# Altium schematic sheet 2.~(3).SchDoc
size 420 x 297 mm
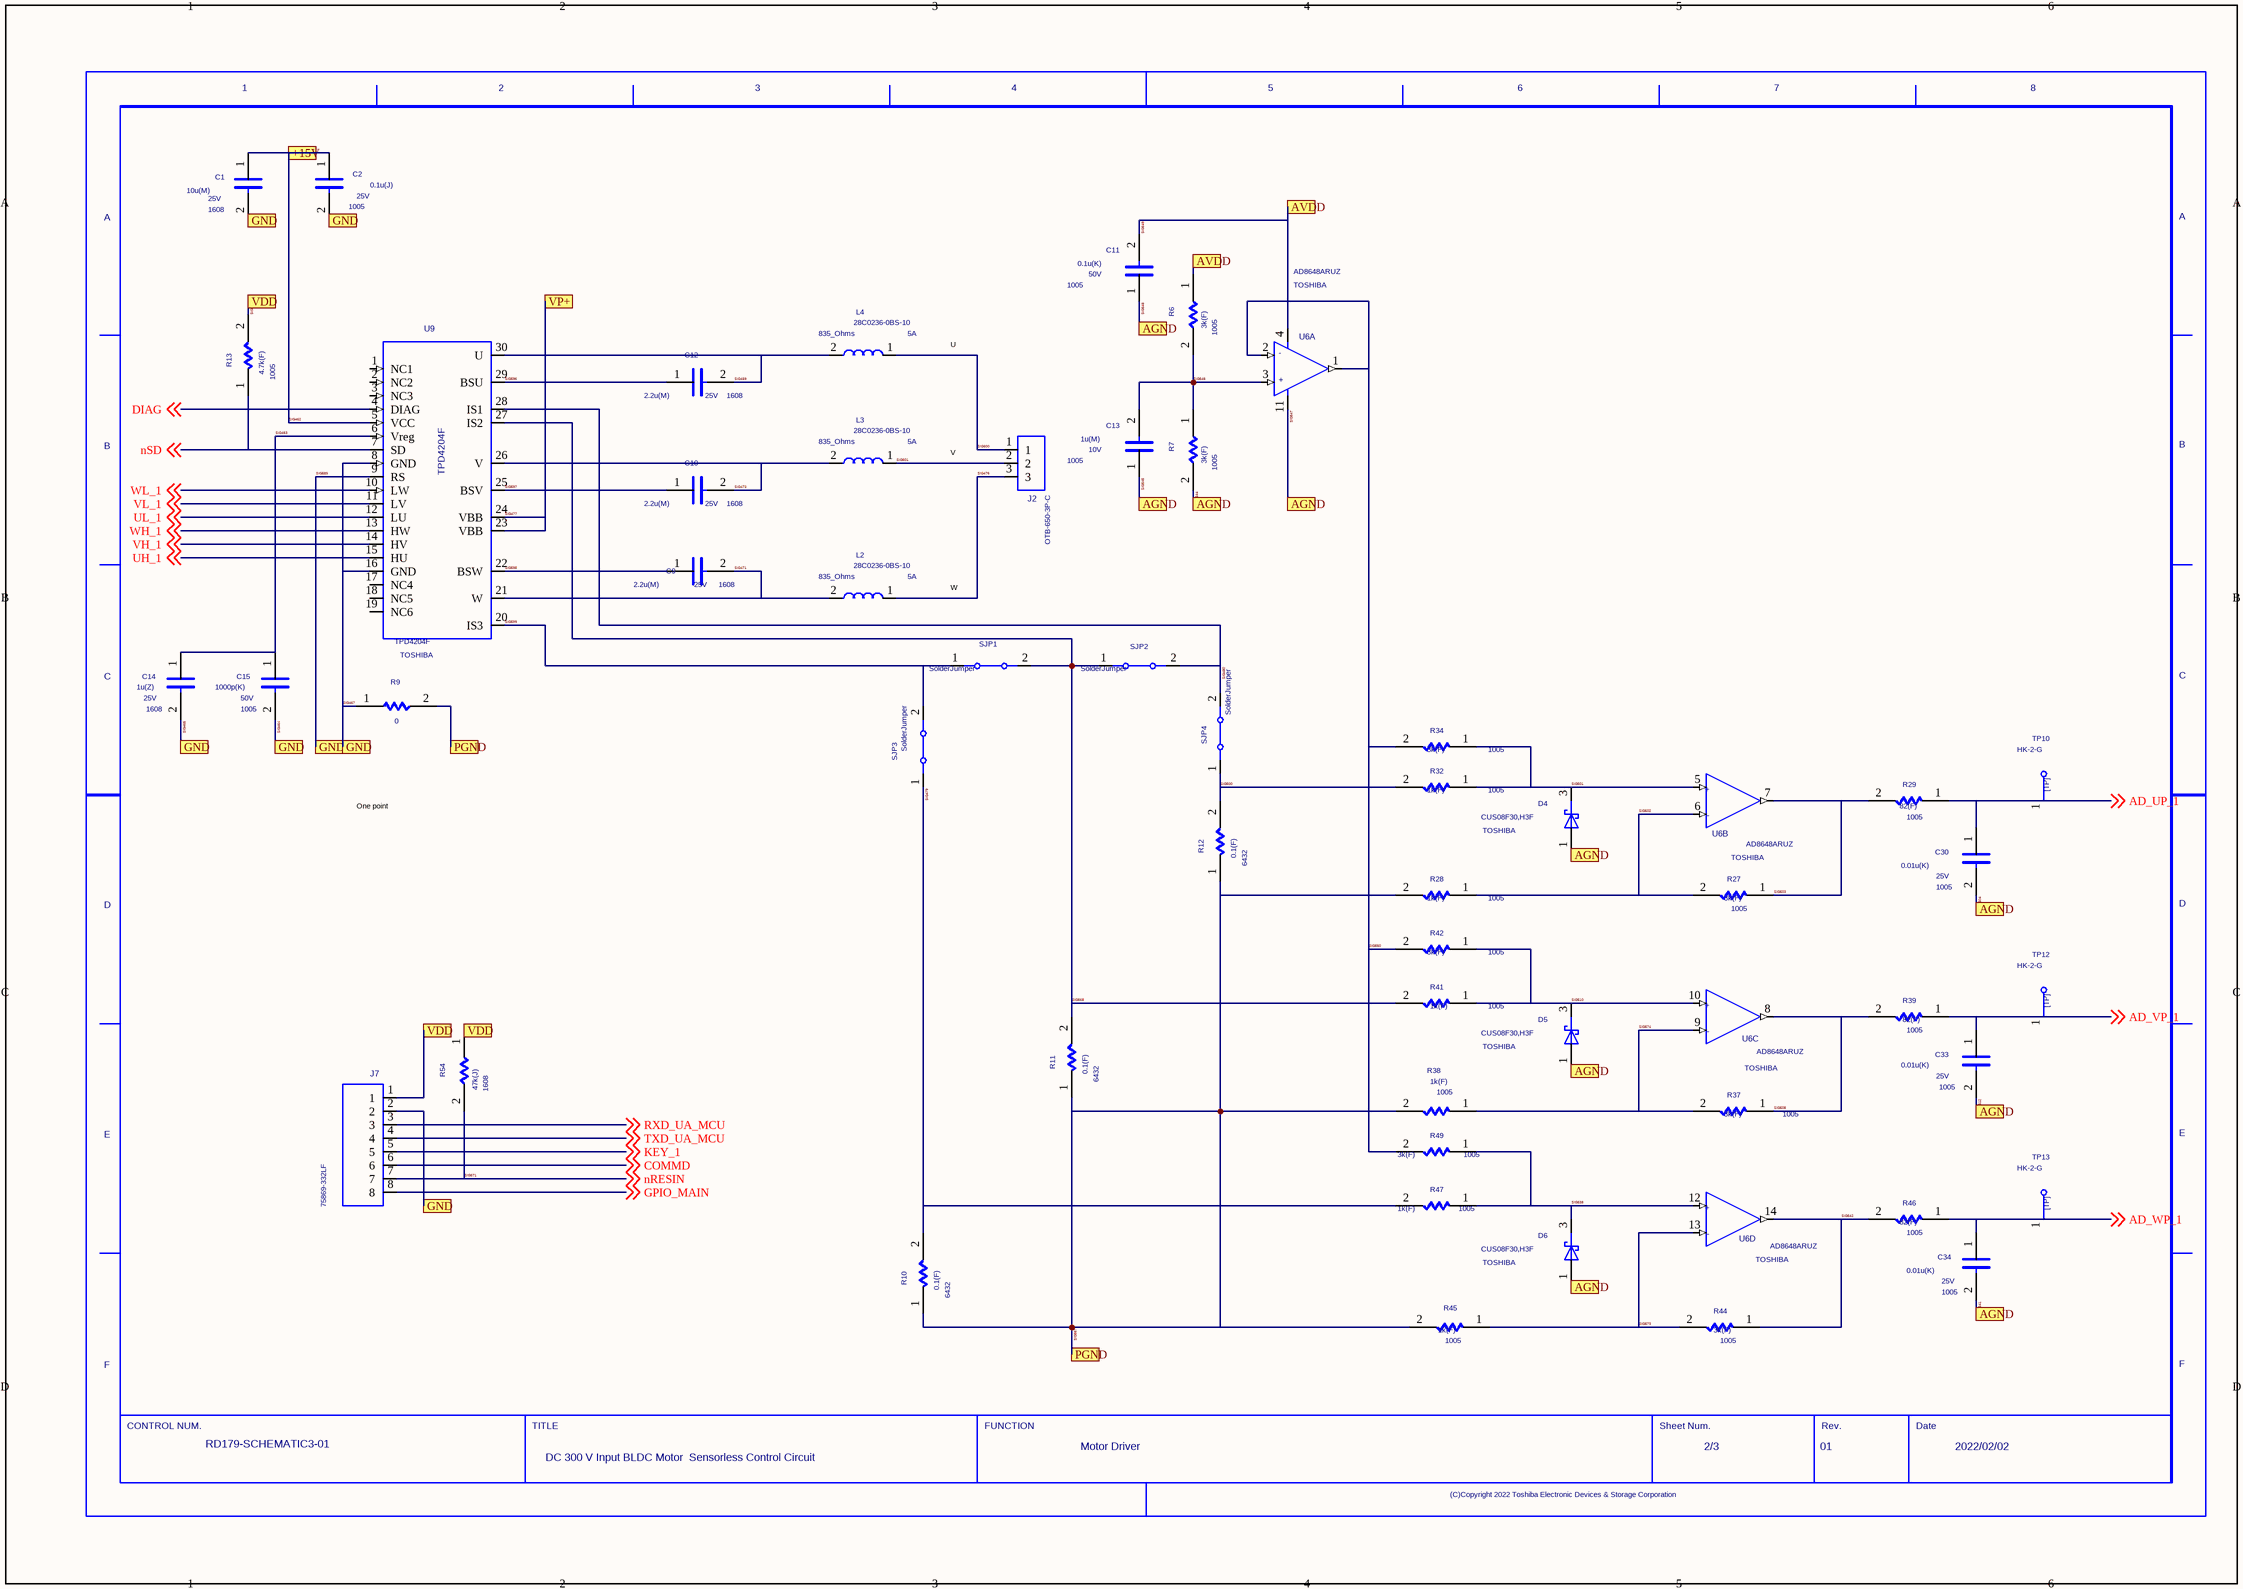
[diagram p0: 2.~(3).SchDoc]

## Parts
C1  SIZECODESMD: 1608  VAL2: 25V  VAL1: 10u(M)  (hidden comment: C)
C2  SIZECODESMD: 1005  VAL2: 25V  VAL1: 0.1u(J)  (hidden comment: C)
C9  SIZECODESMD: 1608  VAL2: 25V  VAL1: 2.2u(M)  (hidden comment: C)
C10  SIZECODESMD: 1608  VAL2: 25V  VAL1: 2.2u(M)  (hidden comment: C)
C11  SIZECODESMD: 1005  VAL2: 50V  VAL1: 0.1u(K)  (hidden comment: C)
C12  SIZECODESMD: 1608  VAL2: 25V  VAL1: 2.2u(M)  (hidden comment: C)
C13  SIZECODESMD: 1005  VAL2: 10V  VAL1: 1u(M)  (hidden comment: C)
C14  SIZECODESMD: 1608  VAL2: 25V  VAL1: 1u(Z)  (hidden comment: C)
C15  SIZECODESMD: 1005  VAL2: 50V  VAL1: 1000p(K)  (hidden comment: C)
C30  SIZECODESMD: 1005  VAL2: 25V  VAL1: 0.01u(K)  (hidden comment: C)
C33  SIZECODESMD: 1005  VAL2: 25V  VAL1: 0.01u(K)  (hidden comment: C)
C34  SIZECODESMD: 1005  VAL2: 25V  VAL1: 0.01u(K)  (hidden comment: C)
D4  USERCOMPTEXT3: TOSHIBA  VAL3: CUS08F30,H3F  (hidden comment: SBD)
D5  USERCOMPTEXT3: TOSHIBA  VAL3: CUS08F30,H3F  (hidden comment: SBD)
D6  USERCOMPTEXT3: TOSHIBA  VAL3: CUS08F30,H3F  (hidden comment: SBD)
J2  OTB-650-3P-C
J7  75869-332LF
L2  VAL3: 28C0236-0BS-10  VAL2: 5A  VAL1: 835_Ohms  (hidden comment: L)
L3  VAL3: 28C0236-0BS-10  VAL2: 5A  VAL1: 835_Ohms  (hidden comment: L)
L4  VAL3: 28C0236-0BS-10  VAL2: 5A  VAL1: 835_Ohms  (hidden comment: L)
R6  SIZECODESMD: 1005  VAL1: 3k(F)  (hidden comment: R)
R7  SIZECODESMD: 1005  VAL1: 3k(F)  (hidden comment: R)
R9  VAL1: 0  (hidden comment: R)
R10  SIZECODESMD: 6432  VAL1: 0.1(F)  (hidden comment: R)
R11  SIZECODESMD: 6432  VAL1: 0.1(F)  (hidden comment: R)
R12  SIZECODESMD: 6432  VAL1: 0.1(F)  (hidden comment: R)
R13  SIZECODESMD: 1005  VAL1: 4.7k(F)  (hidden comment: R)
R27  SIZECODESMD: 1005  VAL1: 3k(F)  (hidden comment: R)
R28  SIZECODESMD: 1005  VAL1: 1k(F)  (hidden comment: R)
R29  SIZECODESMD: 1005  VAL1: 82(F)  (hidden comment: R)
R32  SIZECODESMD: 1005  VAL1: 1k(F)  (hidden comment: R)
R34  SIZECODESMD: 1005  VAL1: 3k(F)  (hidden comment: R)
R37  SIZECODESMD: 1005  VAL1: 3k(F)  (hidden comment: R)
R38  SIZECODESMD: 1005  VAL1: 1k(F)  (hidden comment: R)
R39  SIZECODESMD: 1005  VAL1: 82(F)  (hidden comment: R)
R41  SIZECODESMD: 1005  VAL1: 1k(F)  (hidden comment: R)
R42  SIZECODESMD: 1005  VAL1: 3k(F)  (hidden comment: R)
R44  SIZECODESMD: 1005  VAL1: 3k(F)  (hidden comment: R)
R45  SIZECODESMD: 1005  VAL1: 1k(F)  (hidden comment: R)
R46  SIZECODESMD: 1005  VAL1: 82(F)  (hidden comment: R)
R47  SIZECODESMD: 1005  VAL1: 1k(F)  (hidden comment: R)
R49  SIZECODESMD: 1005  VAL1: 3k(F)  (hidden comment: R)
R54  SIZECODESMD: 1608  VAL1: 47k(J)  (hidden comment: R)
SJP1  VAL3: SolderJumper  (hidden comment: JP)
SJP2  VAL3: SolderJumper  (hidden comment: JP)
SJP3  VAL3: SolderJumper  (hidden comment: JP)
SJP4  VAL3: SolderJumper  (hidden comment: JP)
TP10  VAL3: HK-2-G  (hidden comment: TP)
TP12  VAL3: HK-2-G  (hidden comment: TP)
TP13  VAL3: HK-2-G  (hidden comment: TP)
U6  USERCOMPTEXT3: TOSHIBA  VAL3: AD8648ARUZ  (hidden comment: AD8648ARUZ_1)  (parts A,B,C,D of 4)
U9  USERCOMPTEXT3: TOSHIBA  (hidden comment: TPD4204F)
U?  DATE: 2022/02/02  TITLE: DC 300 V Input BLDC Motor / Sensorless Control Circuit  FUNCTION: Motor Driver  REVISION: 01  SHEETNUMBER: 2/3  DRAWINGNUMBER: RD179-SCHEMATIC3-01  (hidden comment: WAKU_DEF100)

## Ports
+15V, AGND, AVDD, GND, PGND, VDD, VP+

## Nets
AD_UP_1: C30.1 R29.1 TP10.1 ; off-sheet AD_UP_1
AD_VP_1: C33.1 R39.1 TP12.1 ; off-sheet AD_VP_1
AD_WP_1: C34.1 R46.1 TP13.1 ; off-sheet AD_WP_1
COMMD: J7.6 ; off-sheet COMMD
DIAG: U9.4(DIAG) ; off-sheet DIAG
GPIO_MAIN: J7.8 ; off-sheet GPIO_MAIN
KEY_1: J7.5 ; off-sheet KEY_1
nSD: R13.1 U9.7(SD) ; off-sheet nSD
RXD_UA_MCU: J7.3 ; off-sheet RXD_UA_MCU
SIG454: J7.1 R13.2 R54.1 ; port VDD
SIG462: C1.1 C2.1 U9.5(VCC) ; port +15V
SIG463: C14.1 C15.1 U9.6(Vreg)
SIG464: C1.2 C2.2 C14.2 C15.2 J7.2 R9.1 U9.8(GND) U9.9(RS) U9.16(GND) ; port GND  [also labelled SIG465, SIG467, SIG589]
SIG469: C12.2 L4.2 U9.30(U)
SIG471: C9.2 L2.2 U9.21(W)
SIG473: C10.2 L3.2 U9.26(V)
SIG476: J2.3 L2.1
SIG477: U9.23(VBB) U9.24(VBB) ; port VP+
SIG479: R10.2 R47.2 SJP3.1
SIG480: SJP2.2 SJP4.2 U9.28(IS1)
SIG500: R12.2 R32.2 SJP4.1
SIG501: D4.3(C) R32.1 R34.1 U6.5
SIG502: R27.2 R28.1 U6.6
SIG503: R27.1 R29.2 U6.7
SIG504: C11.1 C13.1 C30.2 C33.2 C34.2 D4.1(A) D5.1(A) D6.1(A) R7.2 U6.11(GND) ; port AGND  [also labelled SIG512, SIG541, SIG544, SIG545, SIG547, SIG548]
SIG508: R37.1 R39.2 U6.8
SIG510: D5.3(C) R41.1 R42.1 U6.10
SIG538: D6.3(C) R47.1 R49.1 U6.12
SIG542: R44.1 R46.2 U6.14
SIG546: C13.2 R6.2 R7.1 U6.3(IN+)
SIG549: C11.2 R6.1 U6.4(VCC) ; port AVDD
SIG550: R34.2 R42.2 R49.2 U6.1(OUT) U6.2(IN-)
SIG567: R9.2 R10.1 R11.1 R12.1 R28.2 R38.2 R45.2 ; port PGND
SIG568: R11.2 R41.2 SJP1.2 SJP2.1 U9.27(IS2)
SIG571: J7.7 R54.2 ; off-sheet nRESIN  [also labelled nRESIN]
SIG573: R44.2 R45.1 U6.13
SIG574: R37.2 R38.1 U6.9
SIG596: C12.1 U9.29(BSU)
SIG597: C10.1 U9.25(BSV)
SIG598: C9.1 U9.22(BSW)
SIG599: SJP1.1 SJP3.2 U9.20(IS3)
SIG600: J2.1 L4.1
SIG601: J2.2 L3.1
TXD_UA_MCU: J7.4 ; off-sheet TXD_UA_MCU
UH_1: U9.15(HU) ; off-sheet UH_1
UL_1: U9.12(LU) ; off-sheet UL_1
VH_1: U9.14(HV) ; off-sheet VH_1
VL_1: U9.11(LV) ; off-sheet VL_1
WH_1: U9.13(HW) ; off-sheet WH_1
WL_1: U9.10(LW) ; off-sheet WL_1

Not connected (* = marked no-connect by the designer): U9 1(NC1) 2(NC2) 3(NC3) 17(NC4) 18(NC5) 19(NC6)

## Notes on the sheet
- U
- V
- W
- One point
  ground

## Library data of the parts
C1 C9 C10 C12 C14 = C: OriginalSymbolOrigin: (2540,7620); COMP: CRC-1608-DEF
C2 C11 C13 C15 C30 C33 C34 = C: OriginalSymbolOrigin: (2540,7620); COMP: CRC-1005-DEF
D4-D6 = SBD: SAVEAREA0: -4630,-153,17114,13055; TIME: 14:49:55; UPDATEUSER: fukuda-y; UPDATETIME: 08:16:22; SAVECOUNT: 9; OriginalSymbolOrigin: (5080,5080); COMP: CD-USC-05
J2 = OTB_650_3P_C: COMP: OTB-650-3P_R00; TIME: 16:31:59; UPDATEUSER: t5459927; SAVECOUNT: 1; SAVEAREA0: -6361,-10384,8548,546; OriginalSymbolOrigin: (0,0); INSTANCENAME: I541179
J7 = CON8: COMP: 75869-332LF_R00; ORDER: 0; TIME: 16:31:59; UPDATEUSER: t5459927; SAVECOUNT: 1; SAVEAREA0: -14610,-23317,18939,1279; OriginalSymbolOrigin: (0,0); INSTANCENAME: I16797633
L2-L4 = L: OriginalSymbolOrigin: (2540,5080); COMP: DL-1460-01
R6 R7 R27 R28 R32 R34 R37 R38 R41 R42 R44 R45 R47 R49 = R: OriginalSymbolOrigin: (5080,5080); VAL2: 100mW; COMP: CRC-1005-DEF
R9 = R: OriginalSymbolOrigin: (5080,5080); COMP: CX-0002-75
R10-R12 = R: OriginalSymbolOrigin: (5080,5080); VAL2: 3W; COMP: CR-6432-18
R13 R29 R39 R46 = R: OriginalSymbolOrigin: (5080,5080); VAL2: 63mW; COMP: CRC-1005-DEF
R54 = R: OriginalSymbolOrigin: (5080,5080); VAL2: 100mW; COMP: CRC-1608-DEF
SJP1-SJP4 = JP: OriginalSymbolOrigin: (2540,5080); COMP: CJP-0002-116
TP10 TP12 TP13 = TP: TIME: 16:12:21; UPDATEUSER: fukuda-y; UPDATETIME: 16:18:11; SAVECOUNT: 2; SAVEAREA0: -242,-92,12810,7836; OriginalSymbolOrigin: (0,7620)
U6 = AD8648ARUZ_1: TIME: 16:31:59; UPDATEUSER: t5459927; UPDATETIME: 15:23:55; SAVECOUNT: 10; OriginalSymbolOrigin: (0,0); SAVEAREA0: -20143,-23389,30103,13502; CaptureCellPackProp: AD8648ARUZ_1A
U9 = TPD4204F: TIME: 16:32:01; UPDATEUSER: t5459927; UPDATETIME: 10:39:27; SAVECOUNT: 6; SAVEAREA0: -38352,-57023,57455,-16941; OriginalSymbolOrigin: (0,0)
U? = WAKU_DEF100: PLOTTIME: HH:MM; SAVEAREA0: 147884,-66467,487065,89883; TIME: 14:30:25; UPDATEUSER: t5459927; UPDATETIME: 11:31:06; SAVECOUNT: 7; OriginalSymbolOrigin: (10160,284480)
